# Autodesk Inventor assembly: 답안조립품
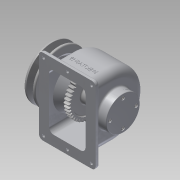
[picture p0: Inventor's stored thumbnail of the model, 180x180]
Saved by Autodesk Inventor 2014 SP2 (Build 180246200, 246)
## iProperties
Created: 2015-09
Part Number: 답안조립품
Document SubType Name: Assembly
Designer: 201-24
Author: 201-24
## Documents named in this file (14)
- C:\Users\201-24\Desktop\450907V1009\답안조립품.iam
- C:\Users\201-24\Desktop\450907V1009\본체.ipt
- C:\Users\201-24\Desktop\450907V1009\뒤커버.ipt
- C:\Users\201-24\Desktop\450907V1009\볼트 M3 x 8.ipt
- C:\Users\201-24\Desktop\450907V1009\베어링 6203.ipt
- C:\Users\201-24\Desktop\450907V1009\축.ipt
- C:\Users\201-24\Desktop\450907V1009\스퍼기어.ipt
- C:\Users\201-24\Desktop\450907V1009\키 - 6 x 6 x 22.ipt
- C:\Users\201-24\Desktop\450907V1009\앞커버.ipt
- C:\Users\201-24\Desktop\450907V1009\볼트 M3 x 10.ipt
- C:\Users\201-24\Desktop\450907V1009\오일 실 17 32 8.ipt
- C:\Users\201-24\Desktop\450907V1009\V-벨트풀리.ipt
- C:\Users\201-24\Desktop\450907V1009\키 - 5 x 5 x 18.ipt
- C:\Users\201-24\Desktop\450907V1009\멈춤나사 - M4x10.ipt
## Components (9 placed, 3 different names)
1. V-벨트풀리:1 — 각도:5
2. ISO 4762 M3 x 8:1 — 각도:1
3. ISO 4762 M3 x 8:2
4. ISO 4762 M3 x 8:3
5. ISO 4762 M3 x 8:4
6. ISO 4762 M3 x 10:1 — 각도:4
7. ISO 4762 M3 x 10:2
8. ISO 4762 M3 x 10:3
9. ISO 4762 M3 x 10:4
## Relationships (3: Angle 3)
- 각도:1 [Angle]: ISO 4762 M3 x 8:1
- 각도:4 [Angle]: ISO 4762 M3 x 10:1
- 각도:5 [Angle]: V-벨트풀리:1
